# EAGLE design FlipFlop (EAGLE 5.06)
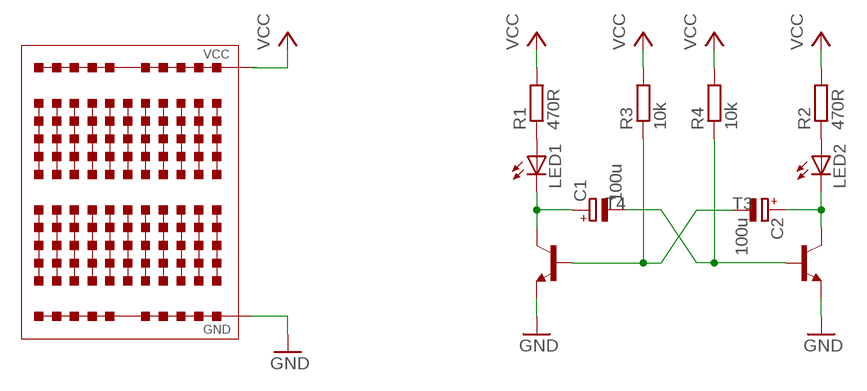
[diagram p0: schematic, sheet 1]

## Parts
C1  100u  CPOL-EUE2.5-5  [E2,5-5]
C2  100u  CPOL-EUE2.5-5  [E2,5-5]
LED1  LED5MM  [LED5MM]
LED2  LED5MM  [LED5MM]
R1  470R  R-EU_0204/7  [0204/7]
R2  470R  R-EU_0204/7  [0204/7]
R3  10k  R-EU_0204/7  [0204/7]
R4  10k  R-EU_0204/7  [0204/7]
T3  -NPN-TO5  [TO5]
T4  -NPN-TO5  [TO5]
U$1  BREADBOARD  [BREADBOARD]

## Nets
GND: T3.1(E) T4.1(E)
N$1: C1.+ LED1.K(C) T4.3(C)
N$2: C2.- R3.1 T4.2(B)
N$3: LED2.A R2.1
N$4: LED1.A R1.1
N$5: C1.- R4.1 T3.2(B)
N$6: C2.+ LED2.K(C) T3.3(C)
VCC: R1.2 R2.2 R3.2 R4.2
Unconnected: U$1.GND U$1.VCC

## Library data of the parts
C1 C2 = rcl:CPOL-EU: POLARIZED CAPACITOR, European symbol
LED1 LED2 = led:LED: LED
R1-R4 = rcl:R-EU_: RESISTOR, European symbol
T3 T4 = transistor:*-NPN-: NPN Transistror BF959 corrected 2008.03.06
U$1 = Breadboard:BREADBOARD

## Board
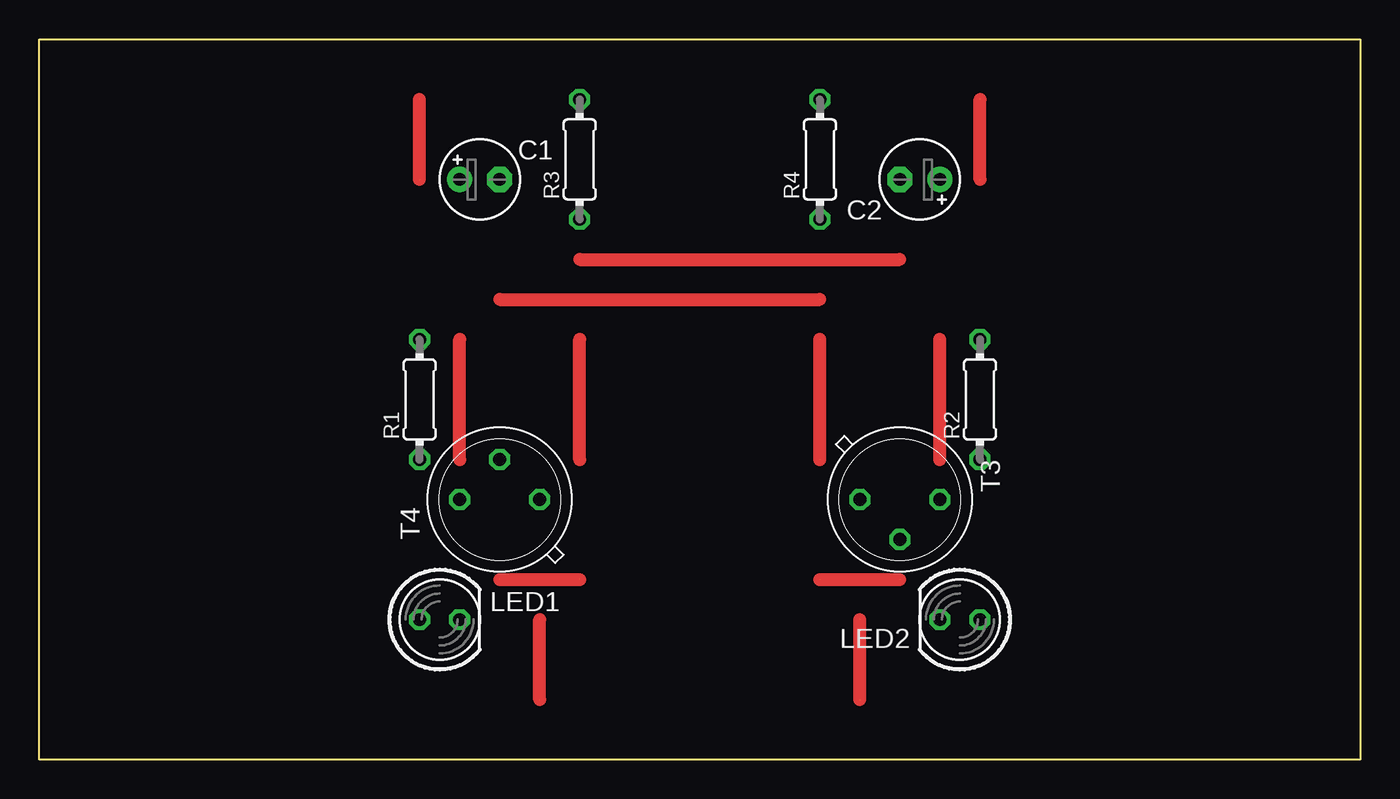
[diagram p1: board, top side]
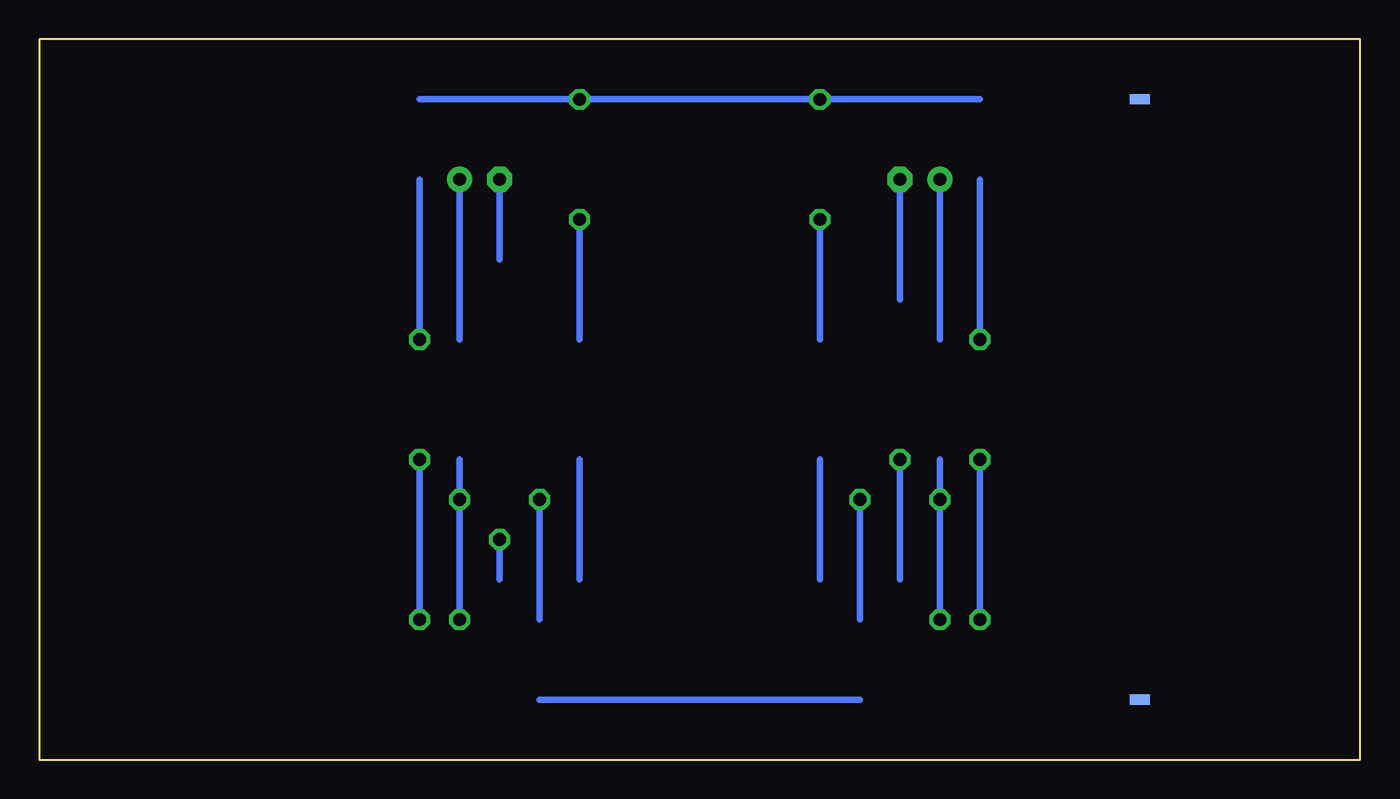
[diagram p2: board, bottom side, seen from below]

Size 83.82 x 45.72 mm. Coordinates in mm from the lower left corner, seen from the top.
Copper layers (1*16): Top 0.035mm / dielectric 1.5mm / Bottom 0.035mm
Design rules "default": minimum track width 10mil, minimum drill 24mil, track to track 8mil, track to pad 8mil, pad to pad 8mil, via to via 8mil, smd to smd 8mil, copper to edge 40mil, drill to drill 8mil, minimum pad ring 10mil, minimum via ring 8mil, stop-mask expansion 4mil, vias tented up to drill 0mil, thermal gap 10mil

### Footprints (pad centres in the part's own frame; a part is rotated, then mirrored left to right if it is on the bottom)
E2,5-5 = drill 0.813 pad 1.6 round: + -1.27,0 | drill 0.813 pad 1.6 octagon: - 1.27,0
LED5MM = drill 0.813 octagon: A -1.27,0; K 1.27,0
0204/7 = drill 0.813 octagon: 1 -3.81,0; 2 3.81,0
TO5 = drill 0.813 octagon: 1 0,-2.54; 2 2.54,0; 3 0,2.54
BREADBOARD = smd 1.27 x 0.635 bottom: GND -27.94,-19.05; VCC -27.94,19.05

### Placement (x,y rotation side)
C1  27.94,36.83 0 top
C2  55.88,36.83 180 top
LED1  25.4,8.89 0 top
LED2  58.42,8.89 180 top
R1  24.13,22.86 90 top
R2  59.69,22.86 90 top
R3  34.29,38.1 90 top
R4  49.53,38.1 90 top
T3  54.61,16.51 270 top
T4  29.21,16.51 90 top
U$1  41.91,22.86 0 top

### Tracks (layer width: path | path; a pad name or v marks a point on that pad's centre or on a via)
GND  (4 unrouted)
  Top 0.813: 31.75,3.81 31.75,8.89 | 52.07,3.81 52.07,8.89
  Bottom 0.406: 31.75,3.81 52.07,3.81 | 31.75,8.89 T4.1 | 52.07,8.89 T3.1
N$1  (2 unrouted)
  Top 0.813: 26.67,19.05 26.67,26.67
  Bottom 0.406: C1.+ 26.67,29.21 26.67,26.67 | LED1.K T4.3 26.67,19.05
N$2  (6 unrouted)
  Top 0.813: 29.21,11.43 34.29,11.43 | 34.29,19.05 34.29,26.67 | 34.29,31.75 54.61,31.75
  Bottom 0.406: 54.61,31.75 C2.- | 34.29,26.67 34.29,31.75 R3.1 | 29.21,11.43 T4.2 | 34.29,11.43 34.29,19.05
N$3
  Bottom 0.406: LED2.A R2.1
N$4
  Bottom 0.406: LED1.A R1.1
N$5  (6 unrouted)
  Top 0.813: 49.53,19.05 49.53,26.67 | 29.21,29.21 49.53,29.21 | 49.53,11.43 54.61,11.43
  Bottom 0.406: 29.21,29.21 C1.- | 49.53,11.43 49.53,19.05 | 54.61,11.43 T3.2 | R4.1 49.53,29.21 49.53,26.67
N$6  (2 unrouted)
  Top 0.813: 57.15,19.05 57.15,26.67
  Bottom 0.406: C2.+ 57.15,31.75 57.15,26.67 | LED2.K T3.3 57.15,19.05
VCC  (4 unrouted)
  Top 0.813: 24.13,36.83 24.13,41.91 | 59.69,36.83 59.69,41.91
  Bottom 0.406: R1.2 24.13,36.83 | R2.2 59.69,36.83 | 59.69,41.91 R4.2 R3.2 24.13,41.91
